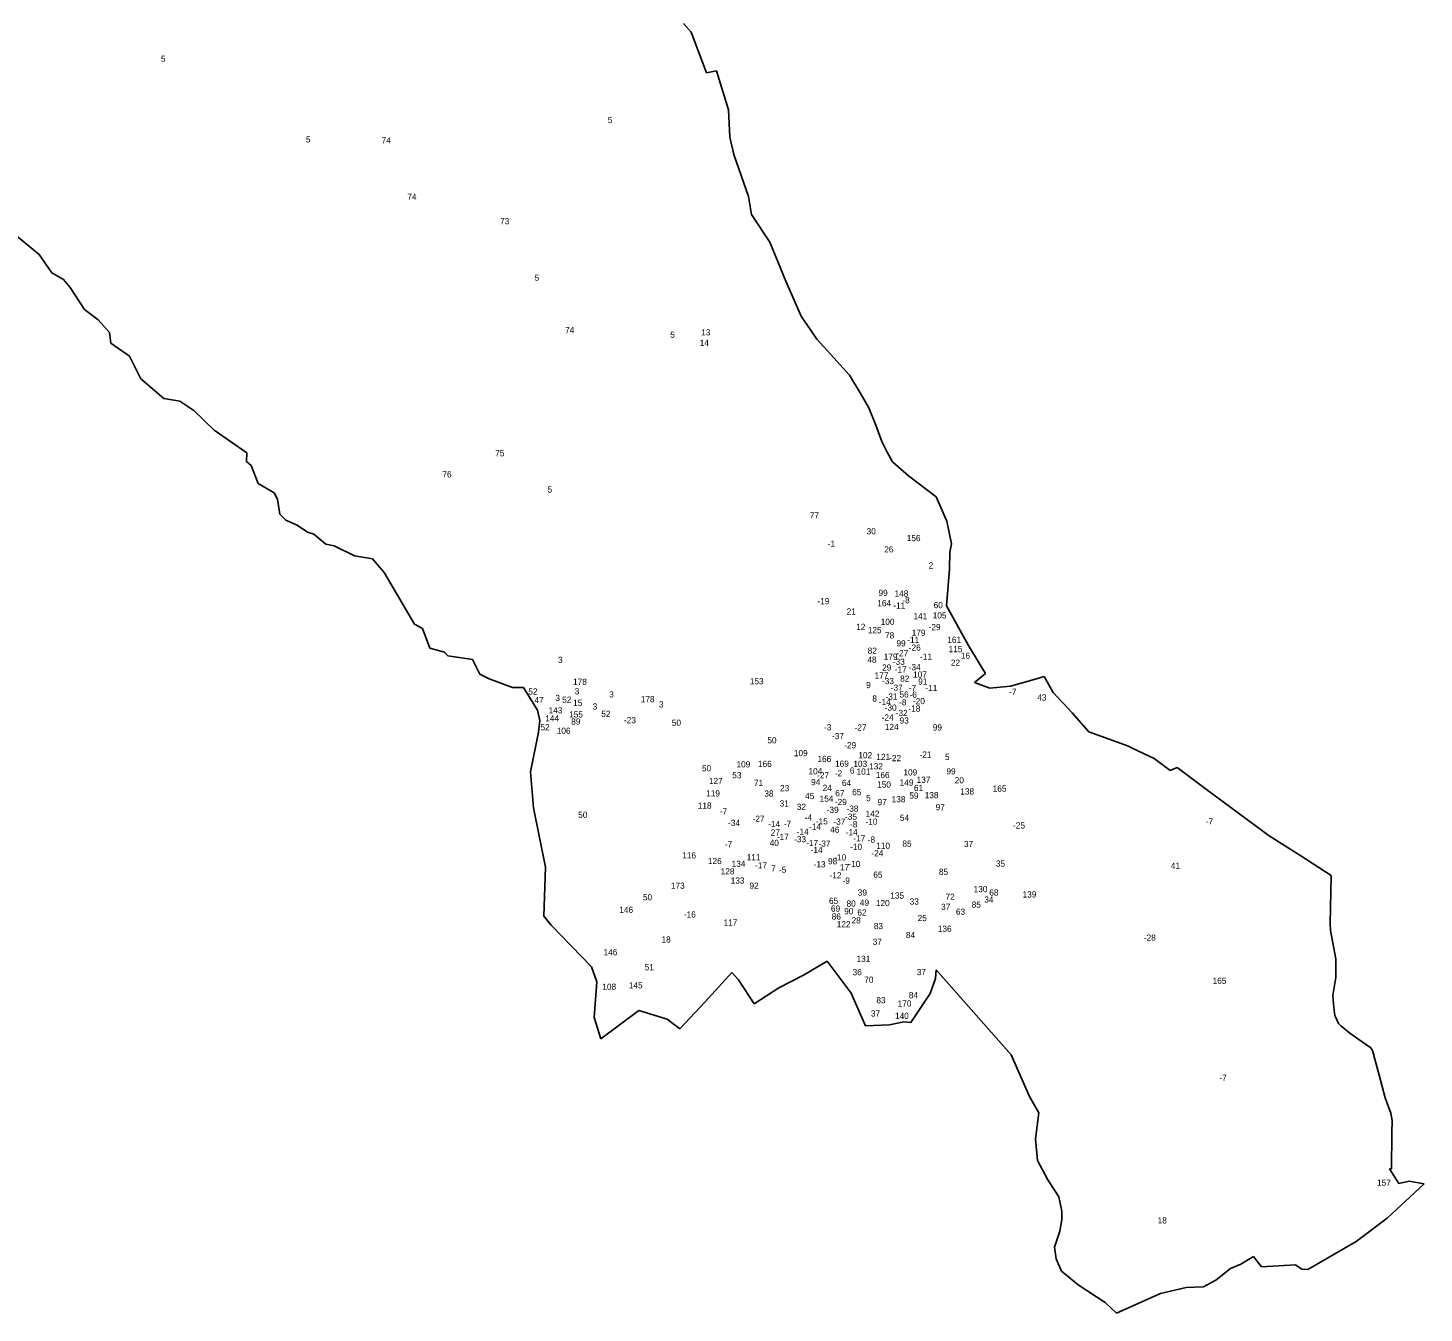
# Model space of a CAD drawing. Extents: x -786993 to -782941, y -974639 to -970914.
# Drawn here: x -784974 to -782941, y -974639 to -972767 of the extents above; entities that cross this region are included whole.
import ezdxf

# ---------------------------------------------------------------- set-up
doc = ezdxf.new("R2010")
doc.units = 0
for name, color, linetype in [('Vrstva 13', 7, 'Continuous'), ('Vrstva 15', 7, 'Continuous'), ('Vrstva 24', 7, 'Continuous')]:
    doc.layers.add(name, color=color, linetype=linetype)

msp = doc.modelspace()

# ---------------------------------------------------------------- linework, layer by layer
at = {"layer": 'Vrstva 13'}
for p, q in [((-784019.74, -972760.61), (-784008.36, -972773.04)), ((-784008.36, -972773.04), (-783986.05, -972832.29)), ((-783986.05, -972832.29), (-783971.79, -972829.4)), ((-783971.79, -972829.4), (-783954, -972886.04)), ((-783954, -972886.04), (-783952.51, -972925.85)), ((-783952.51, -972925.85), (-783946.52, -972951.3)), ((-783946.52, -972951.3), (-783924.93, -973012.24)), ((-783924.93, -973012.24), (-783920.71, -973038.63)), ((-783920.71, -973038.63), (-783893.84, -973079.02)), ((-784991, -973069.56), (-784957.99, -973096.98)), ((-783893.84, -973079.02), (-783870.85, -973135.76)), ((-784957.99, -973096.98), (-784939.45, -973123.68)), ((-784939.45, -973123.68), (-784922.45, -973133.47)), ((-784922.45, -973133.47), (-784912.74, -973144.8)), ((-783870.85, -973135.76), (-783848.32, -973186.66)), ((-784912.74, -973144.8), (-784891.92, -973177.29)), ((-784891.92, -973177.29), (-784872.44, -973192.22)), ((-784872.44, -973192.22), (-784855.7, -973210.65)), ((-783848.32, -973186.66), (-783825.54, -973220.41)), ((-784855.7, -973210.65), (-784853.93, -973225.88)), ((-784853.93, -973225.88), (-784826.62, -973244.83)), ((-783825.54, -973220.41), (-783801, -973247.62)), ((-784826.62, -973244.83), (-784810.22, -973278.02)), ((-783801, -973247.62), (-783778.12, -973272.83)), ((-784810.22, -973278.02), (-784776.52, -973306.74)), ((-783778.12, -973272.83), (-783762.43, -973298.37)), ((-783762.43, -973298.37), (-783749.84, -973320.42)), ((-784776.52, -973306.74), (-784753.19, -973310.57)), ((-784753.19, -973310.57), (-784732.64, -973324.08)), ((-784732.64, -973324.08), (-784703.2, -973352.99)), ((-783749.84, -973320.42), (-783739.47, -973345.76)), ((-784703.2, -973352.99), (-784655.89, -973386.04)), ((-783739.47, -973345.76), (-783730.94, -973369.39)), ((-783730.94, -973369.39), (-783723.07, -973384.75)), ((-784655.89, -973386.04), (-784656.17, -973398.48)), ((-784656.17, -973398.48), (-784649.35, -973404.51)), ((-783723.07, -973384.75), (-783715.46, -973398.93)), ((-783715.46, -973398.93), (-783691.97, -973419.41)), ((-784649.35, -973404.51), (-784639.24, -973430.77)), ((-783691.97, -973419.41), (-783651.57, -973449.86)), ((-784639.24, -973430.77), (-784616.04, -973443.94)), ((-784616.04, -973443.94), (-784611.16, -973453.22)), ((-784611.16, -973453.22), (-784607.4, -973475.37)), ((-783651.57, -973449.86), (-783636.48, -973485.51)), ((-784607.4, -973475.37), (-784598.79, -973484.18)), ((-784598.79, -973484.18), (-784582.6, -973491.18)), ((-784582.6, -973491.18), (-784567.26, -973501.32)), ((-784567.26, -973501.32), (-784558.11, -973504.59)), ((-783636.48, -973485.51), (-783629.52, -973518.47)), ((-784558.11, -973504.59), (-784540.83, -973518.81)), ((-784540.83, -973518.81), (-784528.39, -973521.36)), ((-784528.39, -973521.36), (-784499.11, -973535.89)), ((-783629.52, -973518.47), (-783631.69, -973530.54)), ((-784499.11, -973535.89), (-784472.84, -973540.48)), ((-784472.84, -973540.48), (-784455.74, -973560.1)), ((-783631.69, -973530.54), (-783632.61, -973555.55)), ((-784455.74, -973560.1), (-784411.7, -973635.61)), ((-783632.61, -973555.55), (-783636.83, -973608.72)), ((-783636.83, -973608.72), (-783604.55, -973666.62)), ((-784411.7, -973635.61), (-784400.02, -973641.83)), ((-784400.02, -973641.83), (-784389.08, -973670.25)), ((-784389.08, -973670.25), (-784367.9, -973676.51)), ((-784367.9, -973676.51), (-784362.81, -973681.75)), ((-784362.81, -973681.75), (-784326.84, -973686.9)), ((-783604.55, -973666.62), (-783587.49, -973694.71)), ((-784326.84, -973686.9), (-784316.45, -973708.26)), ((-783587.49, -973694.71), (-783580, -973707.19)), ((-783580, -973707.19), (-783596, -973720.71)), ((-783573.4, -973728.68), (-783596, -973720.71)), ((-783543.68, -973725.66), (-783573.4, -973728.68)), ((-783505.68, -973714.94), (-783543.68, -973725.66)), ((-783494.75, -973711.95), (-783505.68, -973714.94)), ((-783481.32, -973735.17), (-783494.75, -973711.95)), ((-783453.64, -973764.44), (-783481.32, -973735.17)), ((-783429.39, -973792.54), (-783453.64, -973764.44)), ((-783371.73, -973813.41), (-783429.39, -973792.54)), ((-783366.12, -973816.3), (-783371.73, -973813.41)), ((-783334.37, -973831.4), (-783366.12, -973816.3)), ((-783310.87, -973848.73), (-783334.37, -973831.4)), ((-783300.9, -973844.14), (-783310.87, -973848.73)), ((-783256.03, -973877.74), (-783300.9, -973844.14)), ((-783166.81, -973943.89), (-783256.03, -973877.74)), ((-783120.63, -973973.16), (-783166.81, -973943.89)), ((-783076.41, -974001.77), (-783120.63, -973973.16)), ((-783078.22, -974071.93), (-783076.41, -974001.77)), ((-783077.5, -974081.71), (-783078.22, -974071.93)), ((-783069.82, -974122.93), (-783077.5, -974081.71)), ((-783069.88, -974150.16), (-783069.82, -974122.93)), ((-783660.49, -974173.54), (-783652.62, -974151.75)), ((-783652.62, -974151.75), (-783651.84, -974138.89)), ((-783651.84, -974138.89), (-783542.68, -974262.78)), ((-783074.15, -974176.61), (-783069.88, -974150.16)), ((-783688.83, -974215.8), (-783660.49, -974173.54)), ((-783072.51, -974194.01), (-783074.15, -974176.61)), ((-783071.19, -974205.43), (-783072.51, -974194.01)), ((-783069.95, -974208.57), (-783071.19, -974205.43)), ((-783065.68, -974217.17), (-783069.95, -974208.57)), ((-783698.75, -974215.03), (-783688.83, -974215.8)), ((-783062.67, -974220.85), (-783065.68, -974217.17)), ((-783049.45, -974231.35), (-783062.67, -974220.85)), ((-783031.56, -974244.21), (-783049.45, -974231.35)), ((-783019, -974252.81), (-783031.56, -974244.21)), ((-783016.54, -974256.45), (-783019, -974252.81)), ((-783542.68, -974262.78), (-783515.92, -974323.68)), ((-783006.58, -974292.77), (-783016.54, -974256.45)), ((-782997.98, -974325.45), (-783006.58, -974292.77)), ((-783515.92, -974323.68), (-783502.28, -974347.3)), ((-782989.52, -974347.7), (-782997.98, -974325.45)), ((-783502.28, -974347.3), (-783507, -974385.1)), ((-782987.88, -974358.4), (-782989.52, -974347.7)), ((-782988.17, -974376.58), (-782987.88, -974358.4)), ((-783507, -974385.1), (-783504.38, -974416.86)), ((-782988.6, -974428.95), (-782988.17, -974376.58)), ((-783504.38, -974416.86), (-783489.1, -974444.81)), ((-782991.79, -974429.2), (-782988.6, -974428.95)), ((-782978.14, -974450.2), (-782991.79, -974429.2)), ((-783489.1, -974444.81), (-783473.1, -974469.62)), ((-782995, -974500.97), (-782941.24, -974451.11)), ((-782963.05, -974446.79), (-782978.14, -974450.2)), ((-782941.24, -974451.11), (-782963.05, -974446.79)), ((-783473.1, -974469.62), (-783468.83, -974490.88)), ((-783468.83, -974490.88), (-783468.83, -974503.22)), ((-783468.83, -974503.22), (-783471.46, -974519.75)), ((-783040, -974534.97), (-782995, -974500.97)), ((-783471.46, -974519.75), (-783479.59, -974543.38)), ((-783110.46, -974575.8), (-783040, -974534.97)), ((-783479.59, -974543.38), (-783476.9, -974560.18)), ((-783207.94, -974568.04), (-783189.58, -974556.75)), ((-783189.58, -974556.75), (-783178.16, -974571.85)), ((-783476.9, -974560.18), (-783469.42, -974578.16)), ((-783469.42, -974578.16), (-783445.01, -974598.24)), ((-783244.55, -974591.14), (-783223.29, -974574.08)), ((-783223.29, -974574.08), (-783207.94, -974568.04)), ((-783178.16, -974571.85), (-783128.3, -974569.1)), ((-783128.3, -974569.1), (-783119.38, -974575.4)), ((-783119.38, -974575.4), (-783110.46, -974575.8)), ((-783445.01, -974598.24), (-783405.66, -974623.83)), ((-783262.26, -974600.73), (-783244.55, -974591.14)), ((-783389, -974639.19), (-783325.23, -974610.57)), ((-783325.23, -974610.57), (-783287.84, -974601.78)), ((-783287.84, -974601.78), (-783262.26, -974600.73)), ((-783405.66, -974623.83), (-783389, -974639.19))]:
    msp.add_line(p, q, dxfattribs=at)
at = {"layer": 'Vrstva 15'}
for p, q in [((-784316.45, -973708.26), (-784303.01, -973714.95)), ((-784303.01, -973714.95), (-784268.72, -973727.76)), ((-784268.72, -973727.76), (-784252.62, -973727.85)), ((-784252.62, -973727.85), (-784232.37, -973760.69)), ((-784232.37, -973760.69), (-784229.2, -973775.73)), ((-784229.2, -973775.73), (-784230.95, -973792.99)), ((-784230.95, -973792.99), (-784242.38, -973850.81)), ((-784242.38, -973850.81), (-784237.97, -973903.21)), ((-784237.97, -973903.21), (-784220.83, -973989.32)), ((-784220.83, -973989.32), (-784223.12, -974061.08)), ((-784223.12, -974061.08), (-784212.35, -974074.03)), ((-784212.35, -974074.03), (-784153.68, -974134.76)), ((-783844.81, -974146.85), (-783810.3, -974126.6)), ((-783810.3, -974126.6), (-783775.46, -974173.16)), ((-784153.68, -974134.76), (-784145.85, -974156.35)), ((-783988.1, -974185.85), (-783949.13, -974143.14)), ((-783949.13, -974143.14), (-783939.67, -974153.63)), ((-783881.1, -974165.35), (-783844.81, -974146.85)), ((-784145.85, -974156.35), (-784149.64, -974208.49)), ((-783939.67, -974153.63), (-783916.61, -974188.56)), ((-783916.61, -974188.56), (-783881.1, -974165.35)), ((-784025.15, -974224.89), (-783988.1, -974185.85)), ((-783775.46, -974173.16), (-783772.74, -974179.86)), ((-783772.74, -974179.86), (-783754.49, -974220.87)), ((-784149.64, -974208.49), (-784140.11, -974239.75)), ((-784140.11, -974239.75), (-784084.62, -974198.53)), ((-784084.62, -974198.53), (-784043.42, -974210.91)), ((-784043.42, -974210.91), (-784025.15, -974224.89)), ((-783754.49, -974220.87), (-783719.76, -974219.34)), ((-783719.76, -974219.34), (-783698.75, -974215.03))]:
    msp.add_line(p, q, dxfattribs=at)

# ---------------------------------------------------------------- texts
at = {"layer": 'Vrstva 24'}
for s, p in [('5', (-784780.804, -972816.128)), ('5', (-784129.964, -972905.508)), ('5', (-784569.614, -972933.728)), ('74', (-784459.338, -972935.038)), ('74', (-784421.968, -973017.278)), ('73', (-784286.766, -973052.798)), ('5', (-784236.544, -973135.228)), ('74', (-784192.158, -973211.668)), ('5', (-784039.054, -973218.328)), ('13', (-783993.994, -973214.798)), ('14', (-783996.167, -973230.088)), ('75', (-784294.016, -973390.878)), ('76', (-784370.884, -973421.718)), ('5', (-784217.744, -973443.728)), ('77', (-783835.841, -973481.398)), ('30', (-783753.058, -973504.688)), ('-1', (-783809.711, -973522.774)), ('26', (-783727.411, -973530.958)), ('156', (-783694.642, -973514.578)), ('2', (-783662.694, -973554.488)), ('-19', (-783824.698, -973606.434)), ('164', (-783737.524, -973609.378)), ('99', (-783735.816, -973594.388)), ('-11', (-783714.182, -973612.754)), ('148', (-783712.344, -973595.328)), ('-8', (-783701, -973605.054)), ('60', (-783655.462, -973612.238)), ('21', (-783782.104, -973621.518)), ('141', (-783684.826, -973628.378)), ('105', (-783656.816, -973627.208)), ('12', (-783768.234, -973643.868)), ('125', (-783751.402, -973648.678)), ('100', (-783732.55, -973636.558)), ('179', (-783687.386, -973652.488)), ('-29', (-783662.727, -973644.264)), ('78', (-783726.246, -973656.338)), ('99', (-783709.616, -973667.868)), ('-11', (-783693.862, -973662.854)), ('161', (-783635.57, -973662.778)), ('3', (-784202.444, -973691.888)), ('48', (-783751.996, -973691.698)), ('82', (-783751.562, -973678.648)), ('179', (-783728.156, -973687.338)), ('-27', (-783709.815, -973682.224)), ('-26', (-783691.707, -973674.174)), ('-11', (-783675.192, -973687.374)), ('115', (-783633.674, -973676.298)), ('16', (-783615.782, -973685.908)), ('29', (-783730.521, -973703.208)), ('-33', (-783714.92, -973694.714)), ('-17', (-783712.216, -973705.964)), ('-34', (-783691.842, -973702.664)), ('107', (-783685.422, -973713.448)), ('22', (-783630.344, -973696.108)), ('178', (-784180.619, -973723.958)), ('153', (-783923.184, -973723.178)), ('9', (-783753.781, -973728.728)), ('177', (-783741.402, -973714.708)), ('-33', (-783730.72, -973722.874)), ('-37', (-783717.895, -973732.494)), ('82', (-783704.272, -973719.428)), ('-7', (-783691.665, -973733.134)), ('91', (-783677.922, -973723.558)), ('-11', (-783667.492, -973733.024)), ('52', (-784245.782, -973738.098)), ('47', (-784236.79, -973750.588)), ('3', (-784206.364, -973747.548)), ('52', (-784196.512, -973750.008)), ('15', (-784180.594, -973754.698)), ('3', (-784178.194, -973737.708)), ('3', (-784127.994, -973742.258)), ('178', (-784081.969, -973749.198)), ('8', (-783744.784, -973748.328)), ('-14', (-783735.344, -973753.344)), ('-31', (-783725.621, -973745.444)), ('-8', (-783705.73, -973753.804)), ('56', (-783705.219, -973742.318)), ('-6', (-783690.587, -973742.694)), ('-20', (-783685.594, -973752.074)), ('-7', (-783545.645, -973738.624)), ('43', (-783504.466, -973746.798)), ('143', (-784216.254, -973765.518)), ('155', (-784186.374, -973771.438)), ('3', (-784152.094, -973759.898)), ('52', (-784139.532, -973770.568)), ('3', (-784055.514, -973756.848)), ('-30', (-783726.794, -973761.524)), ('-32', (-783710.69, -973769.324)), ('-18', (-783692.201, -973762.924)), ('52', (-784228.042, -973790.188)), ('144', (-784221.037, -973777.108)), ('106', (-784204.334, -973795.248)), ('89', (-784183.329, -973781.898)), ('-23', (-784106.42, -973779.824)), ('50', (-784036.756, -973783.648)), ('-3', (-783815.05, -973790.174)), ('-27', (-783770.685, -973790.654)), ('-24', (-783731.172, -973775.944)), ('124', (-783726.565, -973789.768)), ('93', (-783704.988, -973780.288)), ('99', (-783656.746, -973790.508)), ('50', (-783897.596, -973809.118)), ('-37', (-783803.445, -973803.024)), ('109', (-783859.044, -973827.818)), ('166', (-783824.709, -973836.338)), ('-29', (-783785.727, -973816.314)), ('102', (-783765.086, -973830.908)), ('121', (-783738.944, -973833.378)), ('-22', (-783720.3, -973835.104)), ('-21', (-783676.091, -973829.964)), ('5', (-783638.984, -973833.388)), ('50', (-783992.866, -973849.998)), ('109', (-783942.574, -973844.198)), ('166', (-783911.309, -973843.498)), ('104', (-783837.731, -973854.248)), ('169', (-783799.087, -973843.288)), ('6', (-783777.481, -973853.188)), ('103', (-783772.376, -973843.538)), ('101', (-783767.708, -973854.728)), ('132', (-783749.442, -973847.078)), ('109', (-783699.484, -973855.908)), ('99', (-783636.856, -973854.408)), ('127', (-783982.758, -973868.388)), ('53', (-783948.772, -973860.038)), ('71', (-783917.207, -973871.138)), ('94', (-783833.941, -973870.138)), ('-27', (-783825.195, -973860.224)), ('-2', (-783799.42, -973857.274)), ('64', (-783789.071, -973871.348)), ('166', (-783739.749, -973859.778)), ('150', (-783737.777, -973873.648)), ('149', (-783704.942, -973870.718)), ('137', (-783680.298, -973866.668)), ('20', (-783624.738, -973867.398)), ('119', (-783986.761, -973886.528)), ('38', (-783902.044, -973886.808)), ('23', (-783879.194, -973878.868)), ('45', (-783842.666, -973890.388)), ('154', (-783821.507, -973894.148)), ('24', (-783817.086, -973878.468)), ('67', (-783798.704, -973886.188)), ('65', (-783774.14, -973884.698)), ('5', (-783753.794, -973893.368)), ('138', (-783716.572, -973895.018)), ('59', (-783690.879, -973889.748)), ('61', (-783684.15, -973878.558)), ('138', (-783668.482, -973889.048)), ('138', (-783616.662, -973883.668)), ('165', (-783569.482, -973879.468)), ('50', (-784173.126, -973917.748)), ('118', (-783998.914, -973904.318)), ('-7', (-783966.775, -973912.624)), ('31', (-783879.784, -973901.218)), ('32', (-783854.884, -973906.118)), ('-39', (-783811.187, -973910.524)), ('-29', (-783799.347, -973899.094)), ('-38', (-783782.41, -973908.754)), ('142', (-783754.534, -973916.198)), ('97', (-783737.206, -973899.208)), ('97', (-783652.526, -973906.698)), ('-34', (-783954.792, -973929.484)), ('-27', (-783919.205, -973923.474)), ('-14', (-783896.424, -973931.174)), ('-7', (-783873.635, -973930.604)), ('-4', (-783843.212, -973921.594)), ('-14', (-783836.894, -973934.904)), ('-15', (-783826.991, -973927.194)), ('-37', (-783801.445, -973927.674)), ('-35', (-783784.47, -973920.424)), ('-8', (-783777.22, -973931.524)), ('-10', (-783754.685, -973927.654)), ('54', (-783704.614, -973922.048)), ('-25', (-783539.82, -973933.204)), ('-7', (-783259.105, -973927.314)), ('40', (-783894.23, -973958.598)), ('27', (-783892.728, -973943.618)), ('-17', (-783883.806, -973949.914)), ('-33', (-783858.66, -973953.214)), ('-14', (-783854.874, -973942.384)), ('46', (-783806.133, -973939.438)), ('-14', (-783783.424, -973943.064)), ('-17', (-783772.386, -973951.944)), ('-8', (-783751.49, -973953.814)), ('116', (-784021.621, -973976.878)), ('-7', (-783959.535, -973960.494)), ('-17', (-783841.166, -973958.884)), ('-14', (-783834.564, -973969.004)), ('-37', (-783823.135, -973959.764)), ('-10', (-783777.105, -973964.314)), ('-24', (-783746.092, -973973.724)), ('110', (-783739.118, -973962.918)), ('85', (-783701.002, -973959.768)), ('37', (-783611.266, -973960.238)), ('126', (-783984.26, -973985.078)), ('134', (-783949.605, -973989.008)), ('111', (-783927.694, -973979.448)), ('-17', (-783915.506, -973991.324)), ('7', (-783892.148, -973995.878)), ('-5', (-783880.81, -973997.724)), ('-13', (-783830.251, -973989.774)), ('98', (-783809.248, -973985.388)), ('-10', (-783800.215, -973979.724)), ('17', (-783791.84, -973994.108)), ('-10', (-783779.675, -973989.304)), ('35', (-783564.794, -973988.808)), ('41', (-783310.044, -973992.008)), ('128', (-783965.662, -974000.138)), ('133', (-783951.022, -974013.488)), ('-12', (-783807.031, -974005.884)), ('-9', (-783788.157, -974013.594)), ('65', (-783743.32, -974004.908)), ('85', (-783647.752, -974000.888)), ('50', (-784078.796, -974037.818)), ('173', (-784038.137, -974020.998)), ('92', (-783923.688, -974020.988)), ('39', (-783765.959, -974031.038)), ('135', (-783718.582, -974035.288)), ('72', (-783638.206, -974037.108)), ('130', (-783597.267, -974025.998)), ('68', (-783574.428, -974030.918)), ('139', (-783525.96, -974033.728)), ('146', (-784113.202, -974056.128)), ('65', (-783807.89, -974043.118)), ('69', (-783805.046, -974054.298)), ('90', (-783785.722, -974058.278)), ('80', (-783782.316, -974047.058)), ('62', (-783766.528, -974060.148)), ('49', (-783762.961, -974045.648)), ('120', (-783739.597, -974046.298)), ('33', (-783690.394, -974044.088)), ('37', (-783644.616, -974051.918)), ('63', (-783623.008, -974058.938)), ('85', (-783600.102, -974048.558)), ('34', (-783581.706, -974041.198)), ('-16', (-784019.258, -974062.904)), ('117', (-783961.388, -974074.588)), ('86', (-783803.879, -974065.848)), ('122', (-783796.582, -974077.088)), ('28', (-783774.924, -974071.508)), ('83', (-783742.582, -974079.768)), ('25', (-783678.834, -974068.198)), ('18', (-784051.794, -974099.368)), ('84', (-783695.834, -974092.858)), ('136', (-783649.38, -974083.758)), ('-28', (-783349.29, -974096.714)), ('146', (-784136.132, -974117.918)), ('37', (-783744.246, -974102.678)), ('51', (-784076.182, -974139.678)), ('131', (-783767.744, -974127.608)), ('36', (-783773.461, -974146.998)), ('70', (-783756.48, -974157.928)), ('37', (-783680.016, -974146.838)), ('165', (-783249.152, -974159.538)), ('108', (-784137.966, -974168.238)), ('145', (-784099.374, -974166.128)), ('84', (-783691.634, -974180.478)), ('83', (-783738.842, -974187.728)), ('170', (-783707.864, -974192.588)), ('37', (-783746.816, -974207.118)), ('140', (-783711.699, -974210.668)), ('-7', (-783239.425, -974300.844)), ('157', (-783009.73, -974453.678)), ('18', (-783329.234, -974508.628))]:
    msp.add_text(s, height=9, dxfattribs=at).set_placement(p)

doc.saveas('drawing.dxf')
